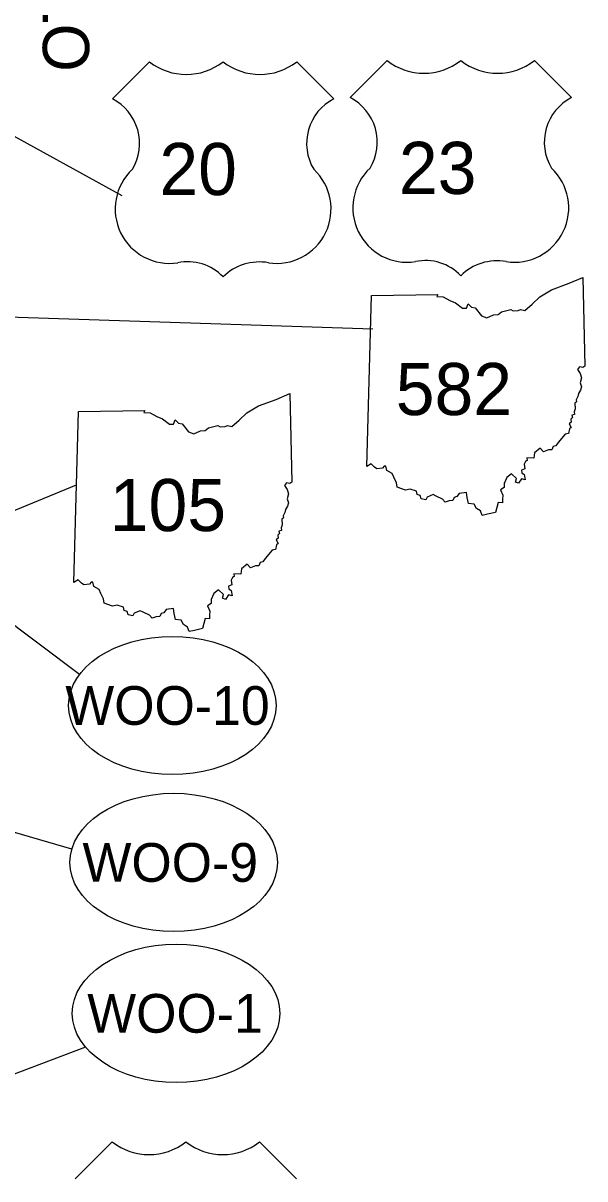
# Model space of a CAD drawing. Extents: x 0 to 851, y 0 to 440.
# Drawn here: x 424 to 464.6, y 193.8 to 277.3 of the extents above; entities that cross this region are included whole.
import ezdxf

# ---------------------------------------------------------------- set-up
doc = ezdxf.new("R2010")
doc.units = 0
for name, color, linetype in [('GM_X_Adjacent_County_Text', 7, 'Continuous'), ('GM_X_State_Route', 7, 'Continuous'), ('GM_X_US_Route', 7, 'Continuous'), ('PV_P_Text', 7, 'Continuous'), ('SH_Data', 7, 'Continuous')]:
    doc.layers.add(name, color=color, linetype=linetype)

msp = doc.modelspace()

# ---------------------------------------------------------------- linework, layer by layer
at = {"layer": 'GM_X_State_Route'}
for points in [[(422.152, 256.129), (449.281, 255.224)], [(421.936, 241.514), (427.868, 243.947)]]:
    msp.add_lwpolyline(points, dxfattribs=at)
at = {"layer": 'GM_X_US_Route'}
msp.add_lwpolyline([(422.401, 269.704), (431.143, 264.882)], dxfattribs=at)
at = {"layer": 'PV_P_Text'}
for p, q in [((433.141, 274.548), (430.462, 271.869)), ((433.141, 274.548), (430.462, 271.869)), ((446.469, 271.869), (443.79, 274.548)), ((446.469, 271.869), (443.79, 274.548)), ((450.321, 274.631), (447.642, 271.952)), ((450.321, 274.631), (447.642, 271.952)), ((463.649, 271.952), (460.97, 274.631)), ((463.649, 271.952), (460.97, 274.631)), ((448.849, 245.27), (449.195, 257.642)), ((448.849, 245.27), (449.195, 257.642)), ((427.67, 236.879), (428.016, 249.251)), ((427.67, 236.879), (428.016, 249.251)), ((430.454, 196.43), (427.775, 193.751)), ((430.454, 196.43), (427.775, 193.751)), ((443.782, 193.751), (441.103, 196.43)), ((443.782, 193.751), (441.103, 196.43))]:
    msp.add_line(p, q, dxfattribs=at)
for points in [[(449.195, 257.642), (453.996, 257.723), (453.921, 257.573), (454.374, 257.542), (454.855, 257.278), (455.262, 257.111), (455.759, 256.717), (456.057, 256.722), (456.183, 257.044), (456.411, 256.795), (456.682, 256.751), (457.15, 256.159), (457.536, 256.03), (457.999, 256.233), (458.345, 256.267), (458.597, 256.467), (459.256, 256.639), (459.44, 256.536), (459.789, 256.557), (459.964, 256.633), (460.268, 256.565), (460.804, 257.015), (461.355, 257.545), (462.203, 258.046), (463.469, 258.52), (464.471, 258.944), (464.615, 252.523)], [(449.195, 257.642), (453.996, 257.723), (453.921, 257.573), (454.374, 257.542), (454.855, 257.278), (455.262, 257.111), (455.759, 256.717), (456.057, 256.722), (456.183, 257.044), (456.411, 256.795), (456.682, 256.751), (457.15, 256.159), (457.536, 256.03), (457.999, 256.233), (458.345, 256.267), (458.597, 256.467), (459.256, 256.639), (459.44, 256.536), (459.789, 256.557), (459.964, 256.633), (460.268, 256.565), (460.804, 257.015), (461.355, 257.545), (462.203, 258.046), (463.469, 258.52), (464.471, 258.944), (464.615, 252.523)], [(464.615, 252.523), (464.468, 252.433), (464.237, 252.476), (464.083, 252.296), (464.274, 251.995), (464.365, 251.678), (464.284, 251.328), (464.364, 251.039), (464.31, 250.798), (464.165, 250.557), (464.115, 250.328), (463.992, 250.087), (464.003, 249.952), (463.885, 249.845), (463.907, 249.443), (463.847, 249.221), (463.868, 249.029), (463.678, 248.978), (463.721, 248.82), (463.6, 248.697), (463.626, 248.486), (463.489, 248.352), (463.622, 248.083), (463.515, 247.997), (463.427, 247.67), (463.183, 247.603), (462.694, 247.004), (462.522, 246.777), (462.329, 246.721), (462.222, 246.488), (461.984, 246.487), (461.623, 246.326), (461.39, 246.604), (460.982, 246.27), (460.935, 245.884), (460.418, 245.896), (460.438, 245.701), (460.323, 245.644), (460.218, 245.449), (460.279, 245.102), (460.037, 245.013), (460.067, 244.812), (460.221, 244.688), (460.29, 244.303), (460.033, 244.381), (459.823, 244.056), (459.606, 244.133), (459.677, 244.408), (459.312, 244.738), (458.966, 244.474), (458.785, 244.05), (458.783, 243.765), (458.525, 243.593), (458.691, 243.191), (458.66, 242.914), (458.665, 242.651), (458.343, 242.66), (458.148, 241.949)], [(464.615, 252.523), (464.468, 252.433), (464.237, 252.476), (464.083, 252.296), (464.274, 251.995), (464.365, 251.678), (464.284, 251.328), (464.364, 251.039), (464.31, 250.798), (464.165, 250.557), (464.115, 250.328), (463.992, 250.087), (464.003, 249.952), (463.885, 249.845), (463.907, 249.443), (463.847, 249.221), (463.868, 249.029), (463.678, 248.978), (463.721, 248.82), (463.6, 248.697), (463.626, 248.486), (463.489, 248.352), (463.622, 248.083), (463.515, 247.997), (463.427, 247.67), (463.183, 247.603), (462.694, 247.004), (462.522, 246.777), (462.329, 246.721), (462.222, 246.488), (461.984, 246.487), (461.623, 246.326), (461.39, 246.604), (460.982, 246.27), (460.935, 245.884), (460.418, 245.896), (460.438, 245.701), (460.323, 245.644), (460.218, 245.449), (460.279, 245.102), (460.037, 245.013), (460.067, 244.812), (460.221, 244.688), (460.29, 244.303), (460.033, 244.381), (459.823, 244.056), (459.606, 244.133), (459.677, 244.408), (459.312, 244.738), (458.966, 244.474), (458.785, 244.05), (458.783, 243.765), (458.525, 243.593), (458.691, 243.191), (458.66, 242.914), (458.665, 242.651), (458.343, 242.66), (458.148, 241.949)], [(428.016, 249.251), (432.817, 249.332), (432.742, 249.182), (433.195, 249.151), (433.676, 248.887), (434.083, 248.72), (434.581, 248.326), (434.878, 248.331), (435.004, 248.653), (435.232, 248.404), (435.503, 248.36), (435.971, 247.768), (436.357, 247.639), (436.82, 247.842), (437.166, 247.876), (437.419, 248.076), (438.077, 248.248), (438.261, 248.145), (438.61, 248.166), (438.785, 248.242), (439.09, 248.174), (439.625, 248.624), (440.176, 249.154), (441.024, 249.655), (442.29, 250.129), (443.292, 250.553), (443.436, 244.132)], [(428.016, 249.251), (432.817, 249.332), (432.742, 249.182), (433.195, 249.151), (433.676, 248.887), (434.083, 248.72), (434.581, 248.326), (434.878, 248.331), (435.004, 248.653), (435.232, 248.404), (435.503, 248.36), (435.971, 247.768), (436.357, 247.639), (436.82, 247.842), (437.166, 247.876), (437.419, 248.076), (438.077, 248.248), (438.261, 248.145), (438.61, 248.166), (438.785, 248.242), (439.09, 248.174), (439.625, 248.624), (440.176, 249.154), (441.024, 249.655), (442.29, 250.129), (443.292, 250.553), (443.436, 244.132)], [(458.148, 241.949), (457.588, 241.814), (457.199, 241.732), (457.062, 242.055), (456.784, 242.225), (456.603, 242.55), (456.203, 242.594), (456.109, 243.04), (456.064, 243.403), (455.518, 243.313), (455.368, 243.092), (455.175, 243.032), (455.062, 242.809), (454.798, 242.791), (454.515, 242.686), (454.33, 242.904), (453.866, 243.124), (453.657, 243.237), (453.221, 243.061), (453.128, 242.853), (452.78, 242.945), (452.699, 243.177), (452.489, 243.247), (452.442, 243.493), (451.993, 243.624), (451.65, 243.572), (451.044, 243.771), (451.007, 244.095), (450.8, 244.49), (450.693, 244.764), (450.31, 244.974), (450.232, 245.3), (450.109, 245.29), (449.997, 245.158), (449.572, 245.097), (449.402, 245.23), (449.164, 245.458), (448.849, 245.27)], [(458.148, 241.949), (457.588, 241.814), (457.199, 241.732), (457.062, 242.055), (456.784, 242.225), (456.603, 242.55), (456.203, 242.594), (456.109, 243.04), (456.064, 243.403), (455.518, 243.313), (455.368, 243.092), (455.175, 243.032), (455.062, 242.809), (454.798, 242.791), (454.515, 242.686), (454.33, 242.904), (453.866, 243.124), (453.657, 243.237), (453.221, 243.061), (453.128, 242.853), (452.78, 242.945), (452.699, 243.177), (452.489, 243.247), (452.442, 243.493), (451.993, 243.624), (451.65, 243.572), (451.044, 243.771), (451.007, 244.095), (450.8, 244.49), (450.693, 244.764), (450.31, 244.974), (450.232, 245.3), (450.109, 245.29), (449.997, 245.158), (449.572, 245.097), (449.402, 245.23), (449.164, 245.458), (448.849, 245.27)], [(443.436, 244.132), (443.289, 244.042), (443.058, 244.085), (442.904, 243.905), (443.095, 243.604), (443.186, 243.287), (443.106, 242.937), (443.185, 242.648), (443.131, 242.407), (442.986, 242.166), (442.936, 241.937), (442.813, 241.696), (442.824, 241.561), (442.706, 241.454), (442.728, 241.052), (442.668, 240.83), (442.689, 240.638), (442.499, 240.587), (442.542, 240.429), (442.421, 240.306), (442.447, 240.095), (442.31, 239.961), (442.443, 239.692), (442.336, 239.606), (442.248, 239.279), (442.004, 239.212), (441.516, 238.613), (441.343, 238.386), (441.15, 238.33), (441.043, 238.097), (440.805, 238.096), (440.444, 237.935), (440.211, 238.213), (439.803, 237.879), (439.756, 237.493), (439.239, 237.505), (439.259, 237.31), (439.144, 237.253), (439.039, 237.058), (439.1, 236.711), (438.858, 236.622), (438.888, 236.421), (439.043, 236.297), (439.111, 235.912), (438.854, 235.99), (438.644, 235.665), (438.428, 235.742), (438.498, 236.017), (438.133, 236.347), (437.787, 236.083), (437.606, 235.659), (437.604, 235.374), (437.346, 235.202), (437.512, 234.8), (437.482, 234.523), (437.487, 234.26), (437.164, 234.269), (436.969, 233.558)], [(443.436, 244.132), (443.289, 244.042), (443.058, 244.085), (442.904, 243.905), (443.095, 243.604), (443.186, 243.287), (443.106, 242.937), (443.185, 242.648), (443.131, 242.407), (442.986, 242.166), (442.936, 241.937), (442.813, 241.696), (442.824, 241.561), (442.706, 241.454), (442.728, 241.052), (442.668, 240.83), (442.689, 240.638), (442.499, 240.587), (442.542, 240.429), (442.421, 240.306), (442.447, 240.095), (442.31, 239.961), (442.443, 239.692), (442.336, 239.606), (442.248, 239.279), (442.004, 239.212), (441.516, 238.613), (441.343, 238.386), (441.15, 238.33), (441.043, 238.097), (440.805, 238.096), (440.444, 237.935), (440.211, 238.213), (439.803, 237.879), (439.756, 237.493), (439.239, 237.505), (439.259, 237.31), (439.144, 237.253), (439.039, 237.058), (439.1, 236.711), (438.858, 236.622), (438.888, 236.421), (439.043, 236.297), (439.111, 235.912), (438.854, 235.99), (438.644, 235.665), (438.428, 235.742), (438.498, 236.017), (438.133, 236.347), (437.787, 236.083), (437.606, 235.659), (437.604, 235.374), (437.346, 235.202), (437.512, 234.8), (437.482, 234.523), (437.487, 234.26), (437.164, 234.269), (436.969, 233.558)], [(436.969, 233.558), (436.409, 233.423), (436.02, 233.341), (435.883, 233.664), (435.605, 233.834), (435.424, 234.159), (435.024, 234.203), (434.93, 234.649), (434.885, 235.012), (434.339, 234.922), (434.189, 234.701), (433.996, 234.641), (433.883, 234.418), (433.619, 234.4), (433.336, 234.295), (433.151, 234.513), (432.687, 234.733), (432.478, 234.846), (432.042, 234.67), (431.949, 234.462), (431.601, 234.554), (431.52, 234.786), (431.31, 234.856), (431.263, 235.102), (430.815, 235.233), (430.471, 235.181), (429.865, 235.38), (429.828, 235.704), (429.622, 236.099), (429.514, 236.373), (429.131, 236.583), (429.053, 236.909), (428.93, 236.899), (428.819, 236.767), (428.393, 236.706), (428.223, 236.839), (427.985, 237.067), (427.67, 236.879)], [(436.969, 233.558), (436.409, 233.423), (436.02, 233.341), (435.883, 233.664), (435.605, 233.834), (435.424, 234.159), (435.024, 234.203), (434.93, 234.649), (434.885, 235.012), (434.339, 234.922), (434.189, 234.701), (433.996, 234.641), (433.883, 234.418), (433.619, 234.4), (433.336, 234.295), (433.151, 234.513), (432.687, 234.733), (432.478, 234.846), (432.042, 234.67), (431.949, 234.462), (431.601, 234.554), (431.52, 234.786), (431.31, 234.856), (431.263, 235.102), (430.815, 235.233), (430.471, 235.181), (429.865, 235.38), (429.828, 235.704), (429.622, 236.099), (429.514, 236.373), (429.131, 236.583), (429.053, 236.909), (428.93, 236.899), (428.819, 236.767), (428.393, 236.706), (428.223, 236.839), (427.985, 237.067), (427.67, 236.879)]]:
    msp.add_lwpolyline(points, dxfattribs=at)
for centre, radius, start, end in [((435.804, 277.932), 4.306, 231.81301, 308.18697), ((435.804, 277.932), 4.306, 231.81301, 308.18697), ((441.128, 277.932), 4.306, 231.81301, 308.18697), ((441.128, 277.932), 4.306, 231.81301, 308.18697), ((452.984, 278.016), 4.306, 231.81301, 308.18697), ((452.984, 278.016), 4.306, 231.81301, 308.18697), ((458.308, 278.016), 4.306, 231.81301, 308.18697), ((458.308, 278.016), 4.306, 231.81301, 308.18697), ((428.787, 268.635), 3.642, 329.11751, 62.61081), ((428.787, 268.635), 3.642, 329.11751, 62.61081), ((448.144, 268.635), 3.642, 117.38919, 210.88249), ((448.144, 268.635), 3.642, 117.38919, 210.88249), ((445.967, 268.718), 3.642, 329.11751, 62.61081), ((445.967, 268.718), 3.642, 329.11751, 62.61081), ((465.325, 268.718), 3.642, 117.38919, 210.88249), ((465.325, 268.718), 3.642, 117.38919, 210.88249), ((434.593, 263.892), 3.93, 133.00455, 278.72816), ((434.593, 263.892), 3.93, 133.00455, 278.72816), ((442.339, 263.892), 3.93, 261.27184, 46.99545), ((442.339, 263.892), 3.93, 261.27184, 46.99545), ((451.773, 263.975), 3.93, 133.00455, 278.72816), ((451.773, 263.975), 3.93, 133.00455, 278.72816), ((459.519, 263.975), 3.93, 261.27184, 46.99545), ((459.519, 263.975), 3.93, 261.27184, 46.99545), ((435.912, 256.568), 3.515, 43.41772, 101.87423), ((435.912, 256.568), 3.515, 43.41772, 101.87423), ((441.092, 256.334), 3.731, 79.96126, 134.74679), ((441.092, 256.334), 3.731, 79.96126, 134.74679), ((453.093, 256.651), 3.515, 43.41772, 101.87423), ((453.093, 256.651), 3.515, 43.41772, 101.87423), ((458.272, 256.418), 3.731, 79.96126, 134.74679), ((458.272, 256.418), 3.731, 79.96126, 134.74679), ((433.117, 199.814), 4.306, 231.81301, 308.18697), ((433.117, 199.814), 4.306, 231.81301, 308.18697), ((438.441, 199.814), 4.306, 231.81301, 308.18697), ((438.441, 199.814), 4.306, 231.81301, 308.18697)]:
    msp.add_arc(centre, radius, start, end, dxfattribs=at)
at = {"layer": 'SH_Data'}
for p, q in [((428.087, 230.225), (415.129, 239.943)), ((427.531, 217.593), (391.934, 227.989)), ((428.53, 203.27), (404.136, 194.116))]:
    msp.add_line(p, q, dxfattribs=at)
for centre in [(434.796, 227.989), (434.892, 216.637), (435.066, 205.723)]:
    msp.add_ellipse(centre, major_axis=(7.5, 0), ratio=0.666667, dxfattribs=at)

# ---------------------------------------------------------------- texts
at = {"layer": 'GM_X_Adjacent_County_Text'}
msp.add_text('OTTAWA COUNTY', height=3.35, rotation=90, dxfattribs=at).set_placement((428.785, 273.823))
at = {"layer": 'PV_P_Text'}
for s, p in [('20', (433.859, 264.901)), ('23', (451.173, 264.984)), ('582', (450.944, 248.991)), ('105', (430.27, 240.6))]:
    msp.add_text(s, height=3.7688, dxfattribs=at).set_placement(p)
at = {"layer": 'SH_Data'}
for s, p in [('WOO-10', (427.061, 226.589)), ('WOO-9', (428.303, 215.237)), ('WOO-1', (428.645, 204.323))]:
    msp.add_text(s, height=2.8, dxfattribs=at).set_placement(p)

doc.saveas('drawing.dxf')
